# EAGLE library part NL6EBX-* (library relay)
6PDT FLATPACK 2AMP DIL RELAY NAiS Single side stable Source: http://www.mew-europe.com/.. en_ds_61014_0003.pdf
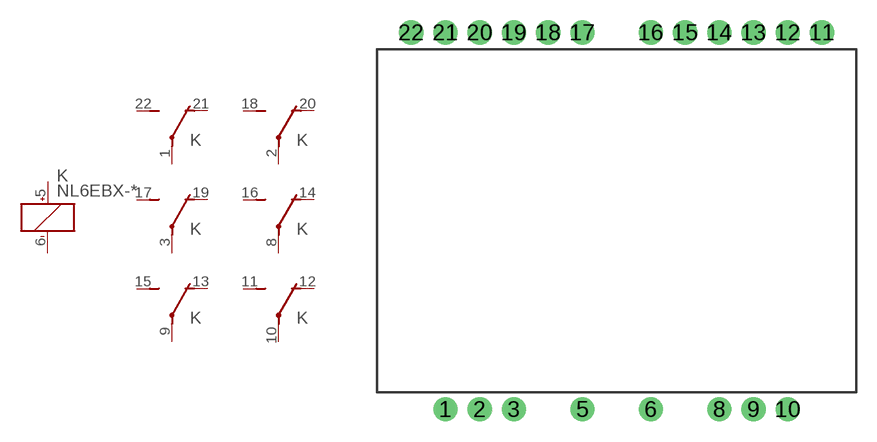
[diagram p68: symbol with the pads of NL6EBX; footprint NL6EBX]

Designator prefix K; gates 1=U 2=U 3=U 4=U 5=U 6=U -=K+-

## NL6EBX-DC5V (OC_FARNELL: unknown; OC_NEWARK: unknown), NL6EBX-DC6V (OC_FARNELL: unknown; OC_NEWARK: unknown), NL6EBX-DC12V (OC_FARNELL: unknown; OC_NEWARK: unknown), NL6EBX-DC24V (OC_FARNELL: unknown; OC_NEWARK: unknown), NL6EBX-DC48V (OC_FARNELL: unknown; OC_NEWARK: unknown), NL6EBX-DC60V (OC_FARNELL: unknown; OC_NEWARK: unknown), NL6EBX-DC110V (OC_FARNELL: unknown; OC_NEWARK: unknown)  [NL6EBX]
1  1:P  pas
2  2:P  pas
3  3:P  pas
5  -:+  pas
6  -:-  pas
8  4:P  pas
9  5:P  pas
10  6:P  pas
11  6:S  pas
12  6:O  pas
13  5:O  pas
14  4:O  pas
15  5:S  pas
16  4:S  pas
17  3:S  pas
18  2:S  pas
19  3:O  pas
20  2:O  pas
21  1:O  pas
22  1:S  pas

## Footprint NL6EBX (pad centres in mm)
6PDT FLATPACK 2AMP DIL RELAY NAiS Single side stable Source: http://www.mew-europe.com/.. en_ds_61014_0003.pdf
drill 1.2 round: 1 -12.7,-13.97; 2 -10.16,-13.97; 3 -7.62,-13.97; 5 -2.54,-13.97; 6 2.54,-13.97; 8 7.62,-13.97; 9 10.16,-13.97; 10 12.7,-13.97; 11 15.24,13.97; 12 12.7,13.97; 13 10.16,13.97; 14 7.62,13.97; 15 5.08,13.97; 16 2.54,13.97; 17 -2.54,13.97; 18 -5.08,13.97; 19 -7.62,13.97; 20 -10.16,13.97; 21 -12.7,13.97; 22 -15.24,13.97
